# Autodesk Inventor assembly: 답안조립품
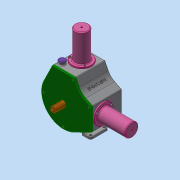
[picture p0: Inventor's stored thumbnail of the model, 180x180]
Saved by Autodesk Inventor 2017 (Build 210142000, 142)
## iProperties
Part Number: 답안조립품
Material: 일반
Document SubType Name: Assembly
Designer: MRC
Author: MRC
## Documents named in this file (13)
- C:\Users\MRC\Desktop\611109V1006\답안조립품.iam
- C:\Users\MRC\Desktop\611109V1006\본체.ipt
- C:\Users\MRC\Desktop\611109V1006\너트 M3.ipt
- C:\Users\MRC\Desktop\611109V1006\베어링 20 x 37 x 9.ipt
- C:\Users\MRC\Desktop\611109V1006\볼트 M3 x 12.ipt
- C:\Users\MRC\Desktop\611109V1006\실린더.ipt
- C:\Users\MRC\Desktop\611109V1006\앞커버.ipt
- C:\Users\MRC\Desktop\611109V1006\축.ipt
- C:\Users\MRC\Desktop\611109V1006\측정게이지.ipt
- C:\Users\MRC\Desktop\611109V1006\커넥팅로드 캡.ipt
- C:\Users\MRC\Desktop\611109V1006\커넥팅로드.ipt
- C:\Users\MRC\Desktop\611109V1006\피스톤 핀.ipt
- C:\Users\MRC\Desktop\611109V1006\피스톤.ipt
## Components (4 placed, 2 different names)
1. 피스톤 핀:1
2. 피스톤:1
3. 피스톤:2
4. 피스톤 핀:2
